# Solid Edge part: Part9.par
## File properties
Author: CADCIM
Template: NORMENG.PAR
Last saved by: CADCIM
Revision: 5
Application: Solid Edge
Density: 0 lbm/in^3
Accuracy: 0.99
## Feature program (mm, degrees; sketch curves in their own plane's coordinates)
sketch for "unnamed RevolvedProtrusion 1" plane through (0, 0, 0) normal (0, -1, 0) x-axis (1, 0, 0)
  line (0, 0) -> (0, 76.2)
  line (0, 76.2) -> (17.145, 76.2)
  line (17.145, 76.2) -> (17.145, 63.5)
  line (17.145, 63.5) -> (12.7, 63.5)
  line (12.7, 63.5) -> (12.7, 0)
  line (12.7, 0) -> (0, 0)
  dimension (linear) = 17.145
revolve "unnamed RevolvedProtrusion 1" add finite 360 deg
sketch for "unnamed Hole 1" plane through (0, 0, 76.2) normal (0, 0, 1) x-axis (0, 1, 0)
hole "unnamed Hole 1" through
chamfer "Chamfer_2" setback 1.524  SetBackValue2 = 45 deg
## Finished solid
Body 1: solid body, 7 faces, 7 edges, 0 vertices.
  Faces by surface: cylinder 3, plane 3, cone 1
  Edges by curve: circle 7
Bounding box of the edges (mm): 34.290 x 34.290 x 76.200, from (-17.145, -17.145, 0) to (17.145, 17.145, 76.2).
Cylindrical faces by radius (mm): R8.001 x1, R12.7 x1, R17.145 x1
Conical faces (half-angle, radius in mm at the cone's reference point): 45 deg R12.7 x1
Planar faces by outward normal: +z 1, -z 2
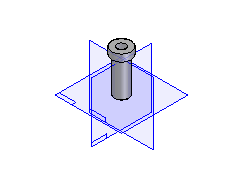
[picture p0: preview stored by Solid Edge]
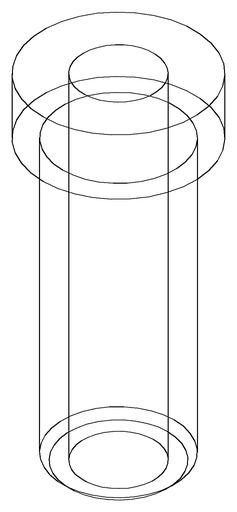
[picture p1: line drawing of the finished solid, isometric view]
